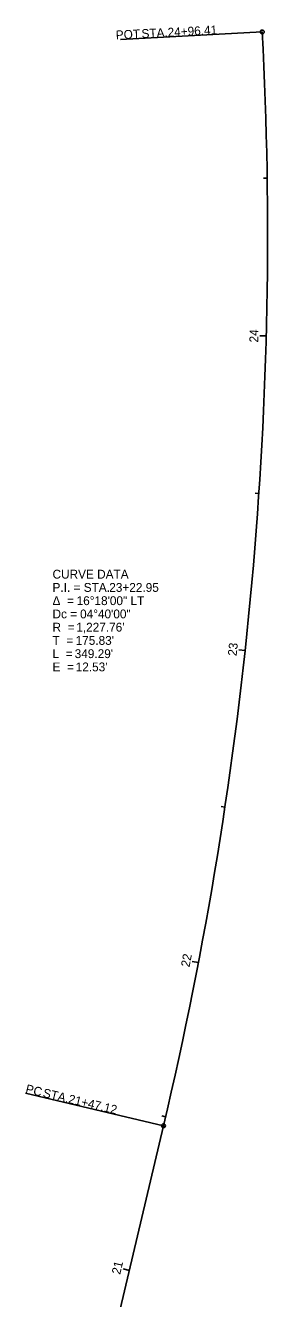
# Model space of a CAD drawing. Extents: x 2124937 to 2129951, y 712967 to 714504.
# Drawn here: x 2128017.2 to 2128093.9, y 714036.7 to 714440.2 of the extents above; entities that cross this region are included whole.
import ezdxf

# ---------------------------------------------------------------- set-up
doc = ezdxf.new("R2010")
doc.units = 0
for name, color, linetype in [('_CIVIL_CONSTRUCTION', 7, 'Continuous'), ('RW_P_Esmt_TMP', 7, 'Continuous'), ('RW_X_Esmt_CH', 7, 'Continuous'), ('RW_X_Fee_WL', 7, 'Continuous'), ('SC_Scratch1', 7, 'Continuous')]:
    doc.layers.add(name, color=color, linetype=linetype)

msp = doc.modelspace()

# ---------------------------------------------------------------- linework, layer by layer
at = {"layer": '_CIVIL_CONSTRUCTION'}
msp.add_line((2128027.08, 713948.3), (2128060.94, 714091.46), dxfattribs=at)
msp.add_arc((2126866.16, 714374.11), 1227.76, 346.69024, 2.99024, dxfattribs=at)
at = {"layer": 'RW_P_Esmt_TMP'}
for p, q in [((2128093.8, 714391.78), (2128092.6, 714391.77)), ((2128093.5, 714341.79), (2128091.5, 714341.84)), ((2128091.16, 714291.84), (2128089.97, 714291.93)), ((2128086.8, 714242.04), (2128084.81, 714242.25)), ((2128080.41, 714192.45), (2128079.22, 714192.63)), ((2128072.01, 714143.17), (2128070.04, 714143.54)), ((2128061.6, 714094.26), (2128060.44, 714094.54)), ((2128050.1, 714045.61), (2128048.15, 714046.07))]:
    msp.add_line(p, q, dxfattribs=at)
at = {"layer": 'RW_X_Esmt_CH'}
for p, q in [((2128092.25, 714438.16), (2128047.31, 714435.81)), ((2128060.94, 714091.46), (2128017.15, 714101.82))]:
    msp.add_line(p, q, dxfattribs=at)
for centre in [(2128092.25, 714438.16), (2128060.94, 714091.46)]:
    msp.add_circle(centre, 0.6, dxfattribs=at)
at = {"layer": 'SC_Scratch1'}
msp.add_line((2128027.08, 713948.3), (2128060.94, 714091.46), dxfattribs=at)
msp.add_arc((2126866.16, 714374.11), 1227.76, 346.69024, 2.99024, dxfattribs=at)

# ---------------------------------------------------------------- texts
at = {"layer": 'RW_P_Esmt_TMP'}
for s, rotation, p in [('24', 88.4912, (2128090.94, 714339.69)), ('23', 83.8245, (2128084.09, 714240.24)), ('22', 79.1578, (2128069.16, 714141.58)), ('21', 76.6902, (2128047.18, 714044.13))]:
    msp.add_text(s, height=2.8, rotation=rotation, dxfattribs=at).set_placement(p)
at = {"layer": 'RW_X_Esmt_CH'}
for s, rotation, p in [('24+96.41', 2.9902, (2128062.3, 714436.63)), ('POT', 2.9902, (2128045.87, 714435.78)), (' STA. ', 2.9902, (2128052.99, 714436.15)), ('PC', 346.6902, (2128017, 714101.9)), (' STA. ', 346.6902, (2128021.48, 714100.84)), ('21+47.12', 346.6902, (2128030.55, 714098.69))]:
    msp.add_text(s, height=2.8, rotation=rotation, dxfattribs=at).set_placement(p)
at = {"layer": 'RW_X_Fee_WL'}
for s, p in [('CURVE DATA', (2128025.74, 714264.88)), ('P.I. = STA. ', (2128025.74, 714260.68)), ('23+22.95', (2128043.73, 714260.68)), ('Δ  = ', (2128025.74, 714256.48)), ('16°18\'00" LT', (2128033.38, 714256.48)), ('Dc = ', (2128025.74, 714252.28)), ('04°40\'00"', (2128034.48, 714252.28)), ('R  = ', (2128025.74, 714248.08)), ("1,227.76'", (2128033.27, 714248.08)), ('T  = ', (2128025.74, 714243.88)), ("175.83'", (2128033.06, 714243.88)), ('L  = ', (2128025.74, 714239.68)), ("349.29'", (2128032.77, 714239.68)), ('E  = ', (2128025.74, 714235.48)), ("12.53'", (2128033.08, 714235.48))]:
    msp.add_text(s, height=2.8, dxfattribs=at).set_placement(p)

doc.saveas('drawing.dxf')
